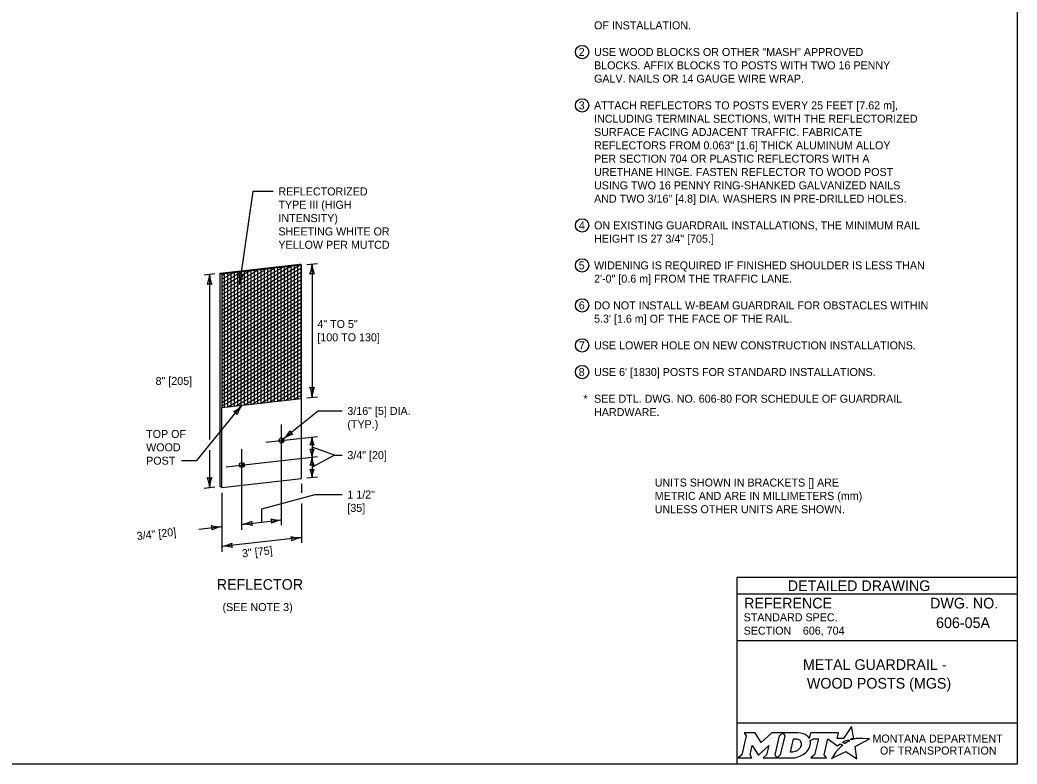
# Model space of a CAD drawing. Extents: x 49991.4 to 50021, y 49987.6 to 50011.4.
# Drawn here: x 50009.28 to 50016.75, y 49987.8 to 49993.38 of the extents above; entities that cross this region are included whole.
import ezdxf

# ---------------------------------------------------------------- set-up
doc = ezdxf.new("R2010")
doc.units = 0
for name, color, linetype in [('Default', 7, 'Continuous'), ('Level 1', 7, 'Continuous'), ('Level 2', 7, 'Continuous'), ('Level 3', 7, 'Continuous'), ('Level 5', 7, 'Continuous')]:
    doc.layers.add(name, color=color, linetype=linetype)

msp = doc.modelspace()

# ---------------------------------------------------------------- linework, layer by layer
at = {"layer": 'Default'}
for points in [[(50014.7056, 49988.0338), (50014.7197, 49988.0104), (50014.6862, 49987.8671), (50014.6605, 49987.8446), (50014.7621, 49987.8446), (50014.7486, 49987.8674), (50014.7648, 49987.9375), (50014.8085, 49987.8685), (50014.8138, 49987.8685), (50014.8889, 49987.938), (50014.8725, 49987.8669), (50014.8478, 49987.8449), (50014.9494, 49987.8449), (50014.9356, 49987.8682), (50014.9688, 49988.0106)], [(50014.9688, 49988.0106), (50014.9941, 49988.0338), (50014.9117, 49988.0338), (50014.8321, 49987.9608), (50014.7876, 49988.0335), (50014.7056, 49988.0338)], [(50015.1077, 49988.0338), (50014.9941, 49988.0338), (50015.0088, 49988.0109), (50014.9749, 49987.8671), (50014.9494, 49987.8449), (50015.06, 49987.8449)], [(50015.5126, 49987.9811), (50015.5023, 49987.9867), (50015.5139, 49987.9895), (50015.5255, 49987.9915), (50015.5081, 49988.0816), (50015.4486, 49987.9903), (50015.4013, 49987.9896), (50015.4116, 49988.0337), (50015.2024, 49988.0338), (50015.1923, 49987.9913), (50015.1865, 49987.9996)], [(50015.1317, 49987.9471), (50015.1305, 49987.939), (50015.1273, 49987.9297), (50015.1231, 49987.9215), (50015.1175, 49987.914), (50015.111, 49987.9071), (50015.1031, 49987.9008), (50015.0948, 49987.8961), (50015.0857, 49987.8922), (50015.0766, 49987.8899), (50015.0674, 49987.889), (50015.0515, 49987.889), (50015.0751, 49987.989), (50015.0911, 49987.989), (50015.0987, 49987.9884), (50015.1063, 49987.9865), (50015.1129, 49987.9835), (50015.119, 49987.9793), (50015.1238, 49987.9743), (50015.1275, 49987.9683), (50015.1302, 49987.9621), (50015.1318, 49987.9547), (50015.1318, 49987.9517), (50015.1317, 49987.9471)], [(50015.1991, 49987.9747), (50015.2237, 49987.9878), (50015.2606, 49987.9878), (50015.232, 49987.8673), (50015.2045, 49987.8446), (50015.3207, 49987.8446), (50015.3037, 49987.8675), (50015.3319, 49987.9877), (50015.4032, 49987.936), (50015.4243, 49987.9511), (50015.444, 49987.9402)], [(50015.3882, 49987.8843), (50015.3729, 49987.8599), (50015.3682, 49987.8524), (50015.3624, 49987.8438), (50015.3601, 49987.8395), (50015.4654, 49987.8926), (50015.5493, 49987.8375), (50015.5362, 49987.9302), (50015.6431, 49987.9886), (50015.5938, 49987.9894), (50015.5637, 49987.9898), (50015.5429, 49987.9901), (50015.5361, 49987.9886), (50015.5312, 49987.9874), (50015.5228, 49987.9851), (50015.5126, 49987.9811)], [(50015.4622, 49987.9535), (50015.4598, 49987.9518), (50015.4415, 49987.9614), (50015.4518, 49987.9671), (50015.4559, 49987.9693), (50015.4645, 49987.9733), (50015.4702, 49987.9759), (50015.4781, 49987.9789), (50015.4854, 49987.9816), (50015.4972, 49987.9742), (50015.4932, 49987.9721), (50015.4886, 49987.9696), (50015.4844, 49987.9674), (50015.4794, 49987.9645), (50015.4775, 49987.9634), (50015.4748, 49987.9618), (50015.4723, 49987.9604), (50015.47, 49987.9588), (50015.4674, 49987.957), (50015.4647, 49987.9552), (50015.4622, 49987.9535)], [(50015.4021, 49987.9004), (50015.4021, 49987.9004)], [(50015.1057, 49987.8522), (50015.1141, 49987.8548), (50015.1271, 49987.8602), (50015.1475, 49987.8712)]]:
    msp.add_lwpolyline(points, dxfattribs=at)
for centre, radius, start, end in [((50015.1308, 49987.9554), 0.0709, 339.53292, 15.85821), ((50015.0868, 49987.9727), 0.1183, 300.91025, 339.13831)]:
    msp.add_arc(centre, radius, start, end, dxfattribs=at)
for centre, major_axis, ratio, start_param, end_param in [((50015.1056, 49987.9864), (0.0834, -0.0037), 0.568097, 0.61298, 1.570796), ((50015.1612, 49987.9937), (0.0361, -0.0295), 0.469099, 1.225588, 1.570796), ((50015.3952, 49987.8923), (-0.00694, -0.00806), 0.008222, 0, 3.137361), ((50015.4119, 49987.9106), (-0.0098, -0.0102), 0.016458, 3.141593, 6.279097), ((50015.4329, 49987.9305), (-0.0112, -0.0097), 0.021651, 3.157348, 6.283185), ((50015.0603, 49987.9932), (0, 0.1484), 0.987302, 3.139398, 3.456847)]:
    msp.add_ellipse(centre, major_axis=major_axis, ratio=ratio, start_param=start_param, end_param=end_param, dxfattribs=at)
at = {"layer": 'Level 1'}
for p, q in [((50010.7766, 49991.4809), (50011.3729, 49991.5474)), ((50011.3855, 49991.5401), (50011.3729, 49991.5474)), ((50010.7892, 49991.4736), (50010.7766, 49991.4809)), ((50010.7766, 49989.8809), (50010.7766, 49991.4809)), ((50011.3855, 49991.5401), (50010.7892, 49991.4736)), ((50010.7892, 49991.2035), (50011.369, 49991.5383)), ((50010.7892, 49991.2324), (50011.307, 49991.5314)), ((50010.7892, 49991.2613), (50011.245, 49991.5245)), ((50010.7892, 49991.1747), (50011.3855, 49991.519)), ((50010.7892, 49991.2901), (50011.1831, 49991.5176)), ((50010.7892, 49991.319), (50011.1211, 49991.5106)), ((50010.7892, 49991.3479), (50011.0591, 49991.5037)), ((50010.7892, 49991.3768), (50010.9971, 49991.4968)), ((50010.7892, 49991.1458), (50011.3855, 49991.4901)), ((50010.7892, 49991.4056), (50010.9352, 49991.4899)), ((50010.7892, 49991.4345), (50010.8732, 49991.483)), ((50010.7892, 49991.4634), (50010.8112, 49991.4761)), ((50010.7892, 49991.4736), (50010.7892, 49990.4736)), ((50010.8082, 49990.4757), (50010.8082, 49991.4757)), ((50010.8332, 49990.4785), (50010.8332, 49991.4785)), ((50010.8582, 49990.4813), (50010.8582, 49991.4813)), ((50010.8832, 49990.4841), (50010.8832, 49991.4841)), ((50010.9082, 49990.4869), (50010.9082, 49991.4869)), ((50010.9332, 49990.4897), (50010.9332, 49991.4897)), ((50010.9582, 49990.4925), (50010.9582, 49991.4925)), ((50010.9832, 49990.4953), (50010.9832, 49991.4953)), ((50011.0082, 49990.4981), (50011.0082, 49991.4981)), ((50011.0332, 49990.5008), (50011.0332, 49991.5008)), ((50011.0582, 49990.5036), (50011.0582, 49991.5036)), ((50011.0832, 49990.5064), (50011.0832, 49991.5064)), ((50011.1082, 49990.5092), (50011.1082, 49991.5092)), ((50011.1332, 49990.512), (50011.1332, 49991.512)), ((50011.1582, 49990.5148), (50011.1582, 49991.5148)), ((50011.1832, 49990.5176), (50011.1832, 49991.5176)), ((50011.2082, 49990.5204), (50011.2082, 49991.5204)), ((50011.2332, 49990.5232), (50011.2332, 49991.5232)), ((50011.2582, 49990.5259), (50011.2582, 49991.5259)), ((50011.2832, 49990.5287), (50011.2832, 49991.5287)), ((50011.3082, 49990.5315), (50011.3082, 49991.5315)), ((50011.3332, 49990.5343), (50011.3332, 49991.5343)), ((50011.3582, 49990.5371), (50011.3582, 49991.5371)), ((50011.3832, 49990.5399), (50011.3832, 49991.5399)), ((50011.3855, 49990.5401), (50011.3855, 49991.5401)), ((50010.7892, 49991.1169), (50011.3855, 49991.4612)), ((50010.7892, 49991.0881), (50011.3855, 49991.4324)), ((50010.7892, 49991.0592), (50011.3855, 49991.4035)), ((50010.7892, 49991.0303), (50011.3855, 49991.3746)), ((50010.7892, 49991.0015), (50011.3855, 49991.3457)), ((50010.7892, 49990.9726), (50011.3855, 49991.3169)), ((50010.7892, 49990.9437), (50011.3855, 49991.288)), ((50010.7892, 49990.9149), (50011.3855, 49991.2591)), ((50010.7892, 49990.886), (50011.3855, 49991.2303)), ((50010.7892, 49990.8571), (50011.3855, 49991.2014)), ((50010.7892, 49990.8283), (50011.3855, 49991.1725)), ((50010.7892, 49990.7994), (50011.3855, 49991.1437)), ((50010.7892, 49990.7705), (50011.3855, 49991.1148)), ((50010.7892, 49990.7417), (50011.3855, 49991.0859)), ((50010.7892, 49990.7128), (50011.3855, 49991.0571)), ((50010.7892, 49990.6839), (50011.3855, 49991.0282)), ((50010.7892, 49990.6551), (50011.3855, 49990.9993)), ((50010.7892, 49990.6262), (50011.3855, 49990.9705)), ((50010.7892, 49990.5973), (50011.3855, 49990.9416)), ((50010.7892, 49990.5685), (50011.3855, 49990.9127)), ((50010.7892, 49990.5396), (50011.3855, 49990.8839)), ((50010.7892, 49990.5107), (50011.3855, 49990.855)), ((50010.7892, 49990.4819), (50011.3855, 49990.8261)), ((50010.8335, 49990.4786), (50011.3855, 49990.7973)), ((50010.8954, 49990.4855), (50011.3855, 49990.7684)), ((50010.9574, 49990.4924), (50011.3855, 49990.7395)), ((50011.0194, 49990.4993), (50011.3855, 49990.7107)), ((50011.0814, 49990.5062), (50011.3855, 49990.6818)), ((50011.1433, 49990.5131), (50011.3855, 49990.6529)), ((50011.2053, 49990.52), (50011.3855, 49990.6241)), ((50011.2673, 49990.5269), (50011.3855, 49990.5952)), ((50010.7892, 49990.4736), (50011.3855, 49990.5401)), ((50011.3293, 49990.5339), (50011.3855, 49990.5663)), ((50011.3855, 49989.9401), (50011.3855, 49990.5401)), ((50010.7892, 49989.8736), (50010.7892, 49990.4736)), ((50010.7892, 49989.8736), (50011.3855, 49989.9401)), ((50010.7892, 49989.8736), (50010.7766, 49989.8809))]:
    msp.add_line(p, q, dxfattribs=at)
msp.add_lwpolyline([(49999.3835, 49998.9992), (50016.7501, 49998.9992), (50016.7501, 49987.7988), (49999.3835, 49987.7988)], close=True, dxfattribs=at)
for centre in [(50011.2355, 49990.2253), (50010.9392, 49990.0413)]:
    msp.add_circle(centre, 0.0187, dxfattribs=at)
for centre, start, end in [((50011.2275, 49990.225), 283.93324, 79.31293), ((50010.9303, 49990.0412), 284.06296, 76.81783)]:
    msp.add_arc(centre, 0.0187, start, end, dxfattribs=at)
at = {"layer": 'Level 2'}
msp.add_line((50015.22, 49988.1057), (50015.22, 49988.1057), dxfattribs=at)
for centre in [(50013.4892, 49993.1385), (50013.4892, 49992.7385), (50013.4892, 49991.8385), (50013.4892, 49991.5385), (50013.4892, 49991.2385), (50013.4892, 49990.9385), (50013.4892, 49990.7385)]:
    msp.add_circle(centre, 0.05, dxfattribs=at)
at = {"layer": 'Level 3'}
for p, q in [((50011.0208, 49992.0929), (50010.9221, 49991.4004)), ((50011.1728, 49992.0929), (50011.0208, 49992.0929)), ((50011.4252, 49991.5446), (50011.5047, 49991.5534)), ((50011.465, 49991.549), (50011.465, 49990.549)), ((50010.6573, 49991.4676), (50010.7368, 49991.4765)), ((50010.6971, 49991.472), (50010.697, 49990.2325)), ((50011.4252, 49990.5446), (50011.5047, 49990.5534)), ((50010.6005, 49990.074), (50010.9396, 49990.4904)), ((50011.5134, 49990.4469), (50011.2502, 49990.2368)), ((50011.5134, 49990.4469), (50011.6896, 49990.4469)), ((50011.465, 49990.2509), (50011.465, 49990.0999)), ((50010.697, 49990.1525), (50010.6971, 49989.872)), ((50011.6335, 49990.1153), (50011.465, 49990.1754)), ((50010.4874, 49990.074), (50010.6005, 49990.074)), ((50011.6335, 49990.1153), (50011.465, 49990.0245)), ((50011.465, 49990.0999), (50011.465, 49989.949)), ((50011.6335, 49990.1153), (50011.6896, 49990.1153)), ((50011.3855, 49989.9001), (50011.3855, 49989.8325)), ((50011.4252, 49989.9446), (50011.5047, 49989.9534)), ((50010.6573, 49989.8676), (50010.7368, 49989.8765)), ((50010.7892, 49989.8336), (50010.7892, 49989.3912)), ((50011.3855, 49989.7525), (50011.3855, 49989.4576)), ((50011.4882, 49989.8198), (50011.6896, 49989.8198)), ((50010.9392, 49989.5961), (50011.2355, 49989.6292)), ((50010.6168, 49989.5602), (50010.7892, 49989.5794)), ((50011.3855, 49989.4977), (50010.7892, 49989.4311))]:
    msp.add_line(p, q, dxfattribs=at)
msp.add_lwpolyline([(50011.0873, 49989.6127), (50011.0873, 49989.7134), (50011.4882, 49989.8198)], dxfattribs=at)
for centre, radius, start, end in [((50011.2429, 49991.5582), 0.2223, 337.45601, 357.63952), ((50011.6977, 49991.5605), 0.233, 182.82731, 202.07716), ((50010.4749, 49991.4812), 0.2223, 337.45601, 357.63952), ((50010.9298, 49991.4835), 0.233, 182.82731, 202.07716), ((50010.9402, 49991.5273), 0.0548, 244.02991, 279.75227), ((50010.6901, 49991.4218), 0.233, 354.7184, 13.96825), ((50011.1408, 49991.36), 0.2223, 149.3471, 169.53061), ((50011.465, 49991.4208), 0.0548, 72.13882, 107.86118), ((50010.6971, 49991.3438), 0.0548, 72.13882, 107.86118), ((50011.465, 49990.6772), 0.0548, 252.13882, 287.86118), ((50011.2323, 49990.5375), 0.233, 2.82731, 22.07716), ((50011.6871, 49990.5398), 0.2223, 157.45601, 177.63952), ((50010.7732, 49990.6378), 0.2223, 298.29816, 318.48166), ((50010.8587, 49990.391), 0.0548, 32.98096, 68.70333), ((50011.1273, 49990.3524), 0.233, 143.66946, 162.91931), ((50011.0961, 49990.4115), 0.233, 311.43157, 330.68142), ((50011.3504, 49990.3168), 0.0548, 200.74308, 236.46544), ((50011.3817, 49990.0575), 0.2223, 106.06027, 126.24378), ((50011.2873, 49990.2582), 0.1779, 337.45601, 357.63952), ((50011.6512, 49990.2601), 0.1864, 182.82731, 202.07716), ((50011.465, 49990.1483), 0.0438, 72.13882, 107.86118), ((50011.465, 49990.2025), 0.0438, 252.13882, 287.86118), ((50011.2788, 49990.0907), 0.1864, 2.82731, 22.07716), ((50011.6427, 49990.0926), 0.1779, 157.45601, 177.63952), ((50011.2873, 49990.1073), 0.1779, 337.45601, 357.63952), ((50011.6512, 49990.1091), 0.1864, 182.82731, 202.07716), ((50011.465, 49989.9974), 0.0438, 72.13882, 107.86118), ((50011.465, 49990.0516), 0.0438, 252.13882, 287.86118), ((50011.2788, 49989.9398), 0.1864, 2.82731, 22.07716), ((50011.6427, 49989.9417), 0.1779, 157.45601, 177.63952), ((50010.6971, 49990.0002), 0.0548, 252.13882, 287.86118), ((50010.4644, 49989.8605), 0.233, 2.82731, 22.07716), ((50010.9192, 49989.8629), 0.2223, 157.45601, 177.63952), ((50010.902, 49989.8261), 0.233, 279.19261, 298.44246), ((50011.0666, 49989.6104), 0.0548, 168.50412, 204.22648), ((50011.22, 49989.851), 0.2223, 253.82131, 274.00482), ((50011.1081, 49989.615), 0.0548, 348.50412, 24.22648), ((50011.2727, 49989.3992), 0.233, 99.19261, 118.44246), ((50010.7737, 49989.8012), 0.2223, 253.82131, 274.00482), ((50010.6618, 49989.5652), 0.0548, 348.50412, 24.22648), ((50010.8264, 49989.3494), 0.233, 99.19261, 118.44246), ((50010.9547, 49989.3744), 0.2223, 73.82131, 94.00482), ((50010.752, 49989.6611), 0.233, 279.19261, 298.44246), ((50010.9166, 49989.4453), 0.0548, 168.50412, 204.22648), ((50011.37, 49989.7194), 0.2223, 253.82131, 274.00482), ((50011.2581, 49989.4834), 0.0548, 348.50412, 24.22648), ((50011.4227, 49989.2677), 0.233, 99.19261, 118.44246), ((50010.8047, 49989.2094), 0.2223, 73.82131, 94.00482)]:
    msp.add_arc(centre, radius, start, end, dxfattribs=at)
at = {"layer": 'Level 5'}
for p, q in [((50011.2355, 49989.5892), (50011.2355, 49990.344)), ((50011.1175, 49990.2121), (50011.5047, 49990.2553)), ((50010.9392, 49989.5561), (50010.9392, 49990.16)), ((50010.8212, 49990.0281), (50011.5047, 49990.1044)), ((50016.7501, 49989.1988), (50014.6501, 49989.1988)), ((50014.6501, 49989.1988), (50014.6501, 49987.7988)), ((50016.7501, 49989.0738), (50014.6501, 49989.0738)), ((50016.3862, 49988.8587), (50016.3862, 49988.8587)), ((50015.1444, 49988.7993), (50015.1444, 49988.7993)), ((50016.7501, 49988.7238), (50014.6501, 49988.7238)), ((50015.7001, 49988.4747), (50015.7001, 49988.4747)), ((50016.7501, 49988.1057), (50014.6501, 49988.1057))]:
    msp.add_line(p, q, dxfattribs=at)

# ---------------------------------------------------------------- texts
at = {"layer": 'Default'}
for s, p in [('MONTANA DEPARTMENT', (50015.6663, 49987.96)), ('OF TRANSPORTATION', (50015.7225, 49987.87))]:
    msp.add_text(s, height=0.06, dxfattribs=at).set_placement(p)
at = {"layer": 'Level 2'}
for s, height, p in [('OF INSTALLATION.', 0.06, (50013.5792, 49993.3085)), ('2', 0.06, (50013.4641, 49993.1085)), ('USE WOOD BLOCKS OR OTHER "MASH" APPROVED ', 0.06, (50013.5792, 49993.1085)), ('BLOCKS. AFFIX BLOCKS TO POSTS WITH TWO 16 PENNY ', 0.06, (50013.5792, 49993.0085)), ('GALV. NAILS OR 14 GAUGE WIRE WRAP.', 0.06, (50013.5792, 49992.9085)), ('3', 0.06, (50013.464, 49992.7085)), ('ATTACH REFLECTORS TO POSTS EVERY 25 FEET [7.62 m], ', 0.06, (50013.5792, 49992.7085)), ('INCLUDING TERMINAL SECTIONS, WITH THE REFLECTORIZED ', 0.06, (50013.5792, 49992.6085)), ('SURFACE FACING ADJACENT TRAFFIC. FABRICATE ', 0.06, (50013.5792, 49992.5085)), ('REFLECTORS FROM 0.063" [1.6] THICK ALUMINUM ALLOY', 0.06, (50013.5792, 49992.4085)), ('PER SECTION 704 OR PLASTIC REFLECTORS WITH A ', 0.06, (50013.5792, 49992.3085)), ('URETHANE HINGE. FASTEN REFLECTOR TO WOOD POST ', 0.06, (50013.5792, 49992.2085)), ('USING TWO 16 PENNY RING-SHANKED GALVANIZED NAILS ', 0.06, (50013.5792, 49992.1085)), ('REFLECTORIZED', 0.06, (50011.2128, 49992.0629)), ('AND TWO 3/16" [4.8] DIA. WASHERS IN PRE-DRILLED HOLES.', 0.06, (50013.5792, 49992.0085)), ('TYPE III (HIGH', 0.06, (50011.2128, 49991.9629)), ('INTENSITY)', 0.06, (50011.2128, 49991.8629)), ('4', 0.06, (50013.4652, 49991.8085)), ('ON EXISTING GUARDRAIL INSTALLATIONS, THE MINIMUM RAIL ', 0.06, (50013.5792, 49991.8085)), ('SHEETING WHITE OR', 0.06, (50011.2128, 49991.7629)), ('HEIGHT IS 27 3/4" [705.]', 0.06, (50013.5792, 49991.7085)), ('YELLOW PER MUTCD', 0.06, (50011.2128, 49991.6629)), ('5', 0.06, (50013.4643, 49991.5085)), ('WIDENING IS REQUIRED IF FINISHED SHOULDER IS LESS THAN ', 0.06, (50013.5792, 49991.5085)), ('2\'-0" [0.6 m] FROM THE TRAFFIC LANE.', 0.06, (50013.5792, 49991.4085)), ('6', 0.06, (50013.4647, 49991.2085)), ('DO NOT INSTALL W-BEAM GUARDRAIL FOR OBSTACLES WITHIN ', 0.06, (50013.5792, 49991.2085)), ("5.3' [1.6 m] OF THE FACE OF THE RAIL.", 0.06, (50013.5792, 49991.1085)), ('4" TO 5"', 0.06, (50011.505, 49991.069)), ('[100 TO 130]', 0.06, (50011.505, 49990.969)), ('7', 0.06, (50013.4654, 49990.9085)), ('USE LOWER HOLE ON NEW CONSTRUCTION INSTALLATIONS.', 0.06, (50013.5792, 49990.9085)), ('8', 0.06, (50013.4642, 49990.7085)), ("USE 6' [1830] POSTS FOR STANDARD INSTALLATIONS.", 0.06, (50013.5792, 49990.7085)), ('8" [205]', 0.06, (50010.2921, 49990.642)), ('*', 0.06, (50013.4994, 49990.5085)), ('SEE DTL. DWG. NO. 606-80 FOR SCHEDULE OF GUARDRAIL ', 0.06, (50013.5792, 49990.5085)), ('3/16" [5] DIA.', 0.06, (50011.7296, 49990.4169)), ('HARDWARE.', 0.06, (50013.5792, 49990.4085)), ('(TYP.)', 0.06, (50011.7296, 49990.3169)), ('TOP OF', 0.06, (50010.2212, 49990.244)), ('WOOD', 0.06, (50010.2212, 49990.144)), ('3/4" [20]', 0.06, (50011.7296, 49990.0853)), ('POST', 0.06, (50010.2212, 49990.044)), ('UNITS SHOWN IN BRACKETS [] ARE ', 0.06, (50014.0338, 49989.8798)), ('METRIC AND ARE IN MILLIMETERS (mm) ', 0.06, (50014.0338, 49989.7798)), ('UNLESS OTHER UNITS ARE SHOWN.', 0.06, (50014.0338, 49989.6798)), ('REFLECTOR', 0.08, (50010.7502, 49989.1061)), ('(SEE NOTE 3)', 0.06, (50010.7938, 49988.9461)), ('606-05A', 0.08, (50016.1428, 49988.8187)), ('606, 704', 0.06, (50015.1444, 49988.7693)), ('METAL GUARDRAIL - ', 0.08, (50015.1452, 49988.5047)), ('WOOD POSTS (MGS)', 0.08, (50015.1746, 49988.3647))]:
    msp.add_text(s, height=height, dxfattribs=at).set_placement(p)
for s, rotation, p in [('1 1/2"', 0, (50011.7296, 49989.7898)), ('[35]', 0, (50011.7296, 49989.6898)), (' 3/4" [20]', 6.3653, (50010.1325, 49989.476)), ('3" [75]', 6.3563, (50010.9438, 49989.3478))]:
    msp.add_text(s, height=0.06, rotation=rotation, dxfattribs=at).set_placement(p)
at = {"layer": 'Level 5'}
for s, height, p in [('DETAILED DRAWING', 0.0799, (50015.0311, 49989.0963)), ('REFERENCE', 0.08, (50014.7037, 49988.9654)), ('DWG. NO.', 0.08, (50016.0979, 49988.9654)), ('STANDARD SPEC.', 0.06, (50014.7004, 49988.8694)), ('SECTION', 0.06, (50014.7004, 49988.7694))]:
    msp.add_text(s, height=height, dxfattribs=at).set_placement(p)

doc.saveas('drawing.dxf')
